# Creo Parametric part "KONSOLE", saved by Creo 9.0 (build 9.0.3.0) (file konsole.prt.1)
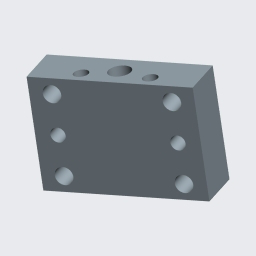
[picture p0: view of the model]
Units: millimeter Kilogram Sec (mmKs); MM, KILOGRAM, SECS
Materials in the file: STAHL

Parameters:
  SCHRAUBEN_GROESSE = "M4x.7"
  METRISCH = "JA"
  WERKSTOFF = "Stahl"
  ERSTELLER = "ARINDA"
  BENENNUNG = "XXX"
  TEILETYP = "K"
  PTC_MASTER_MATERIAL = "STAHL"

Other parameters: STEIGUNG, BOHR_DURCHM, GEWINDEDURCHMESSER, GEWINDEGÄNGE_PRO_INCH, MASSE, BOHRER_SPITZENWINKEL, BOHR_TIEFE, GEWINDETIEFE, GEWINDELÄNGE, ANSENKDURCHMESSER, ANSENKTIEFE

Created from: ARINDA_STARTTEIL.PRT

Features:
  1. coordinate system
  2. datum plane "RECHTS_Y-Z"
  3. datum plane "OBEN_X-Z"
  4. datum plane "VORNE_X-Y"
  5. datum axis
  6. datum axis
  7. datum axis
  8. datum point "PNT0"
  9. extrusion "Profil 1"
  10. sketch "Skizze 1"
  11. pattern "Muster 1"
  12. hole "Bohrung 1"
  13. hole "Bohrung 1 [8]"
  14. sketch "Skizze 2"
  15. pattern "Muster 2"
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
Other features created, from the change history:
  coordinate system "CS1"
  hole "Bohrung 2"
  hole "Bohrung 2 [11]"
  hole "Bohrung 2 [12]"
  hole "Bohrung 2 [13]"
  sketch "Skizze 3"
  hole "Bohrung 3"
  pattern "Muster 3"
  hole "Bohrung 3 [9]"
  hole "Bohrung 4"

Other named items: KONSOLE, LEISTE, STIFT, LEISTE_GEWINDE, STIFTBOHRUNG, TISCH, TISCH_GEWINDE, HÖHENVERSTELLUNG, A_X, A_Y, A_Z, CS0

Layers: 01_ACHSEN, 01_ACHSEN_STD, 01_EBENEN_STD, 01_KOORDSYS_STD, 01_KURVEN, 01_PUNKTE_STD, GEWINDE, SAMMELFLÄCHEN, VOLUMENGEOMETRIE

Notes: M4x.7 | GEWINDEBOHREN | DURCH |  BOHREN (  | 3.300 | DURCH |   -(  |  ) BOHRUNG | M4x.7 | GEWINDEBOHREN | 6.000 |  BOHREN (  | 3.300 | 9.500 |   -(  |  ) BOHRUNG | M6x1 | GEWINDEBOHREN | DURCH |  BOHREN (  | 5.000 | DURCH |   -(  |  ) BOHRUNG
